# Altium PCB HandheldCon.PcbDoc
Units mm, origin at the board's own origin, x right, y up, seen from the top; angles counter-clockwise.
Board outline 100 x 100 mm, 2 copper layers (Top Layer, Bottom Layer); 39 components, 35 nets, 244 pads, 30 vias.
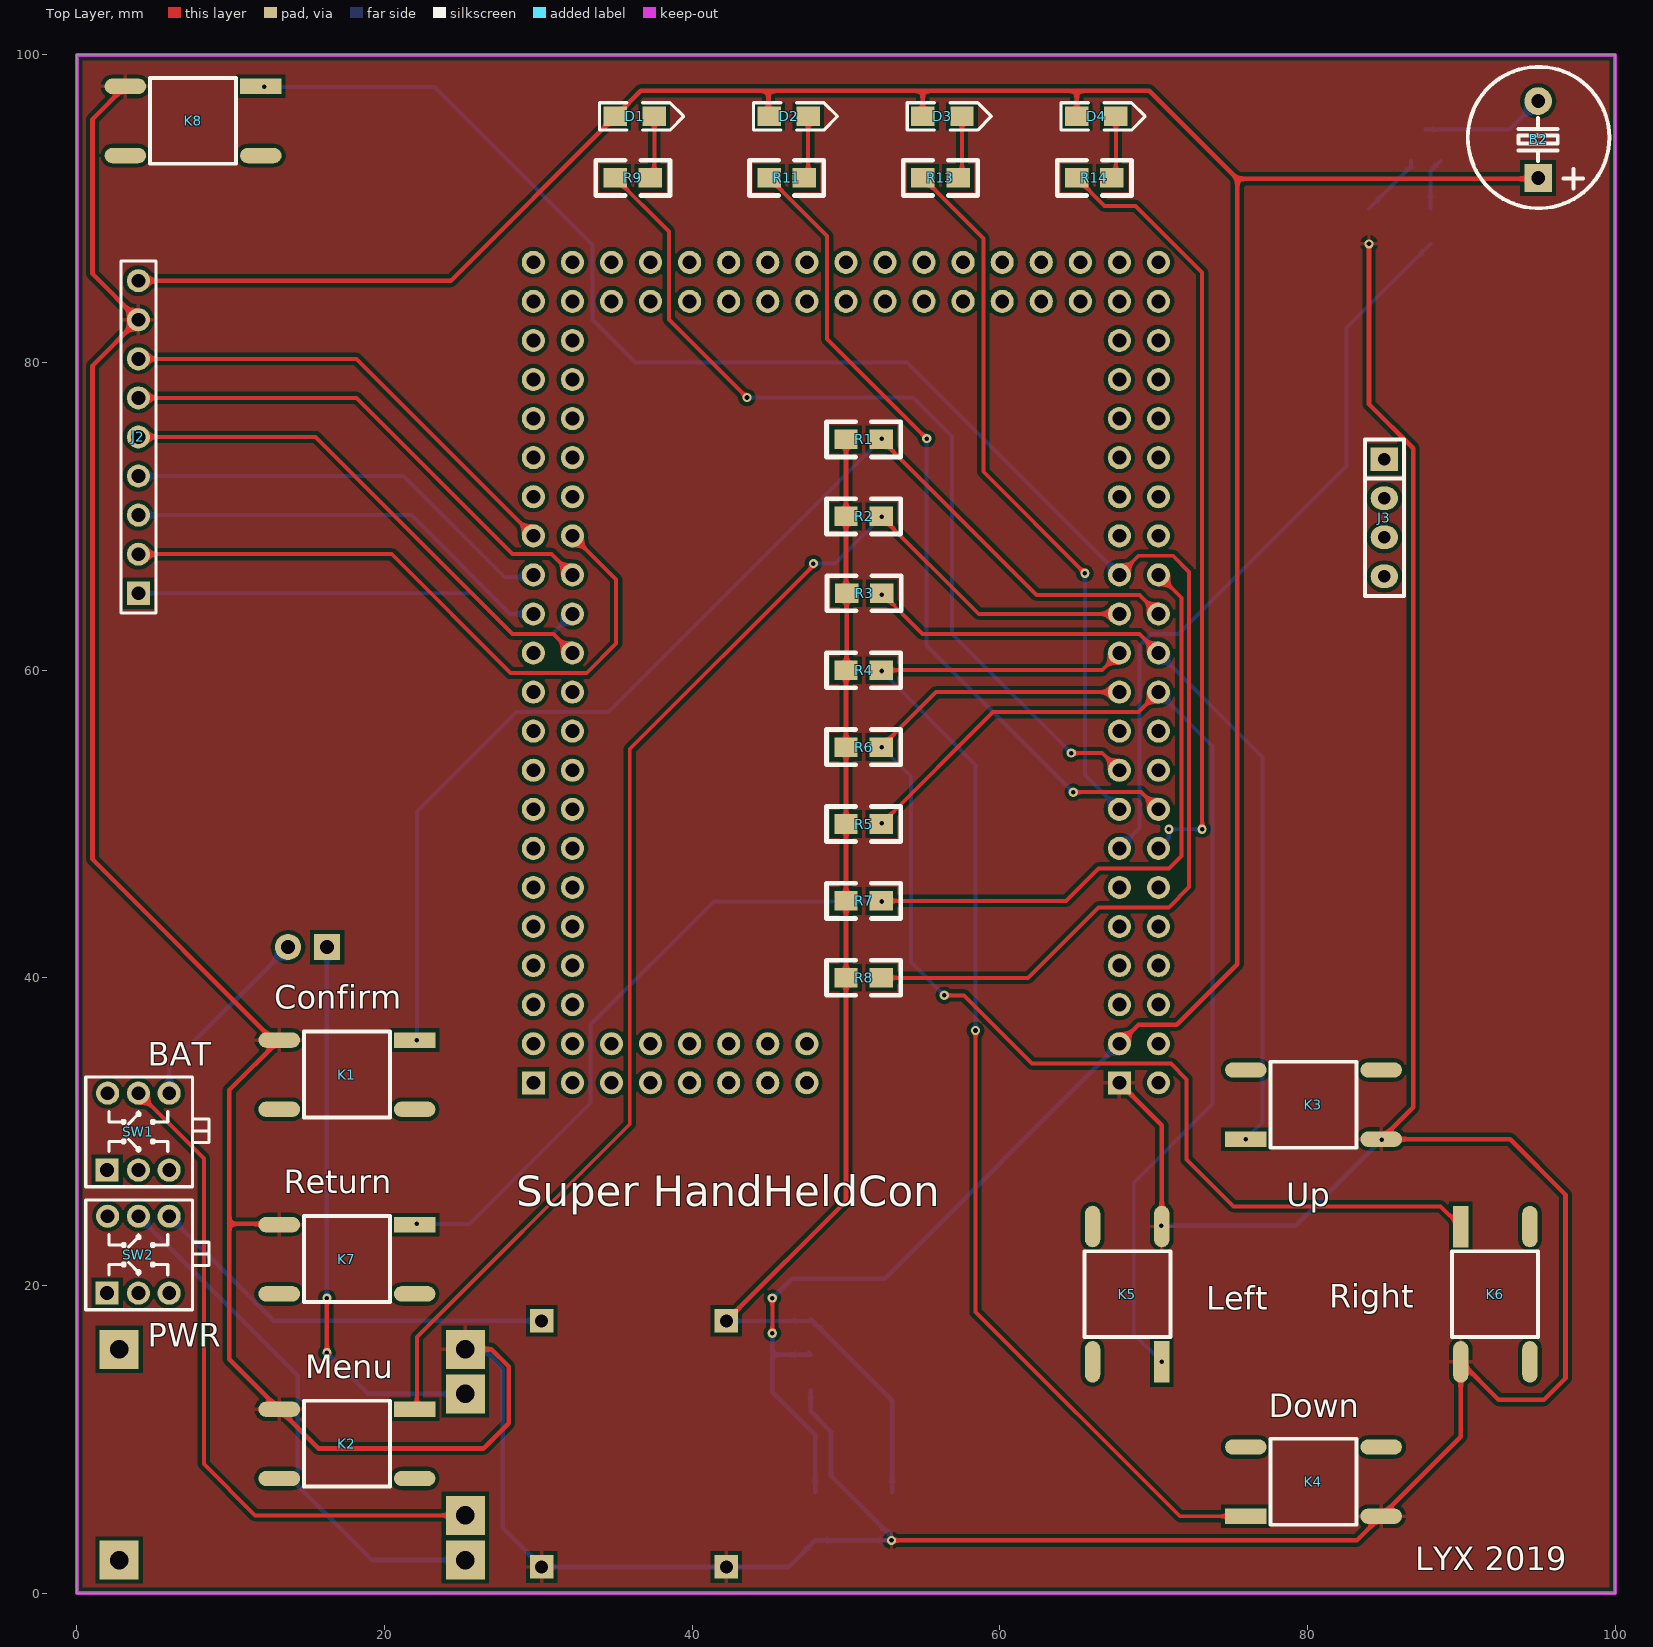
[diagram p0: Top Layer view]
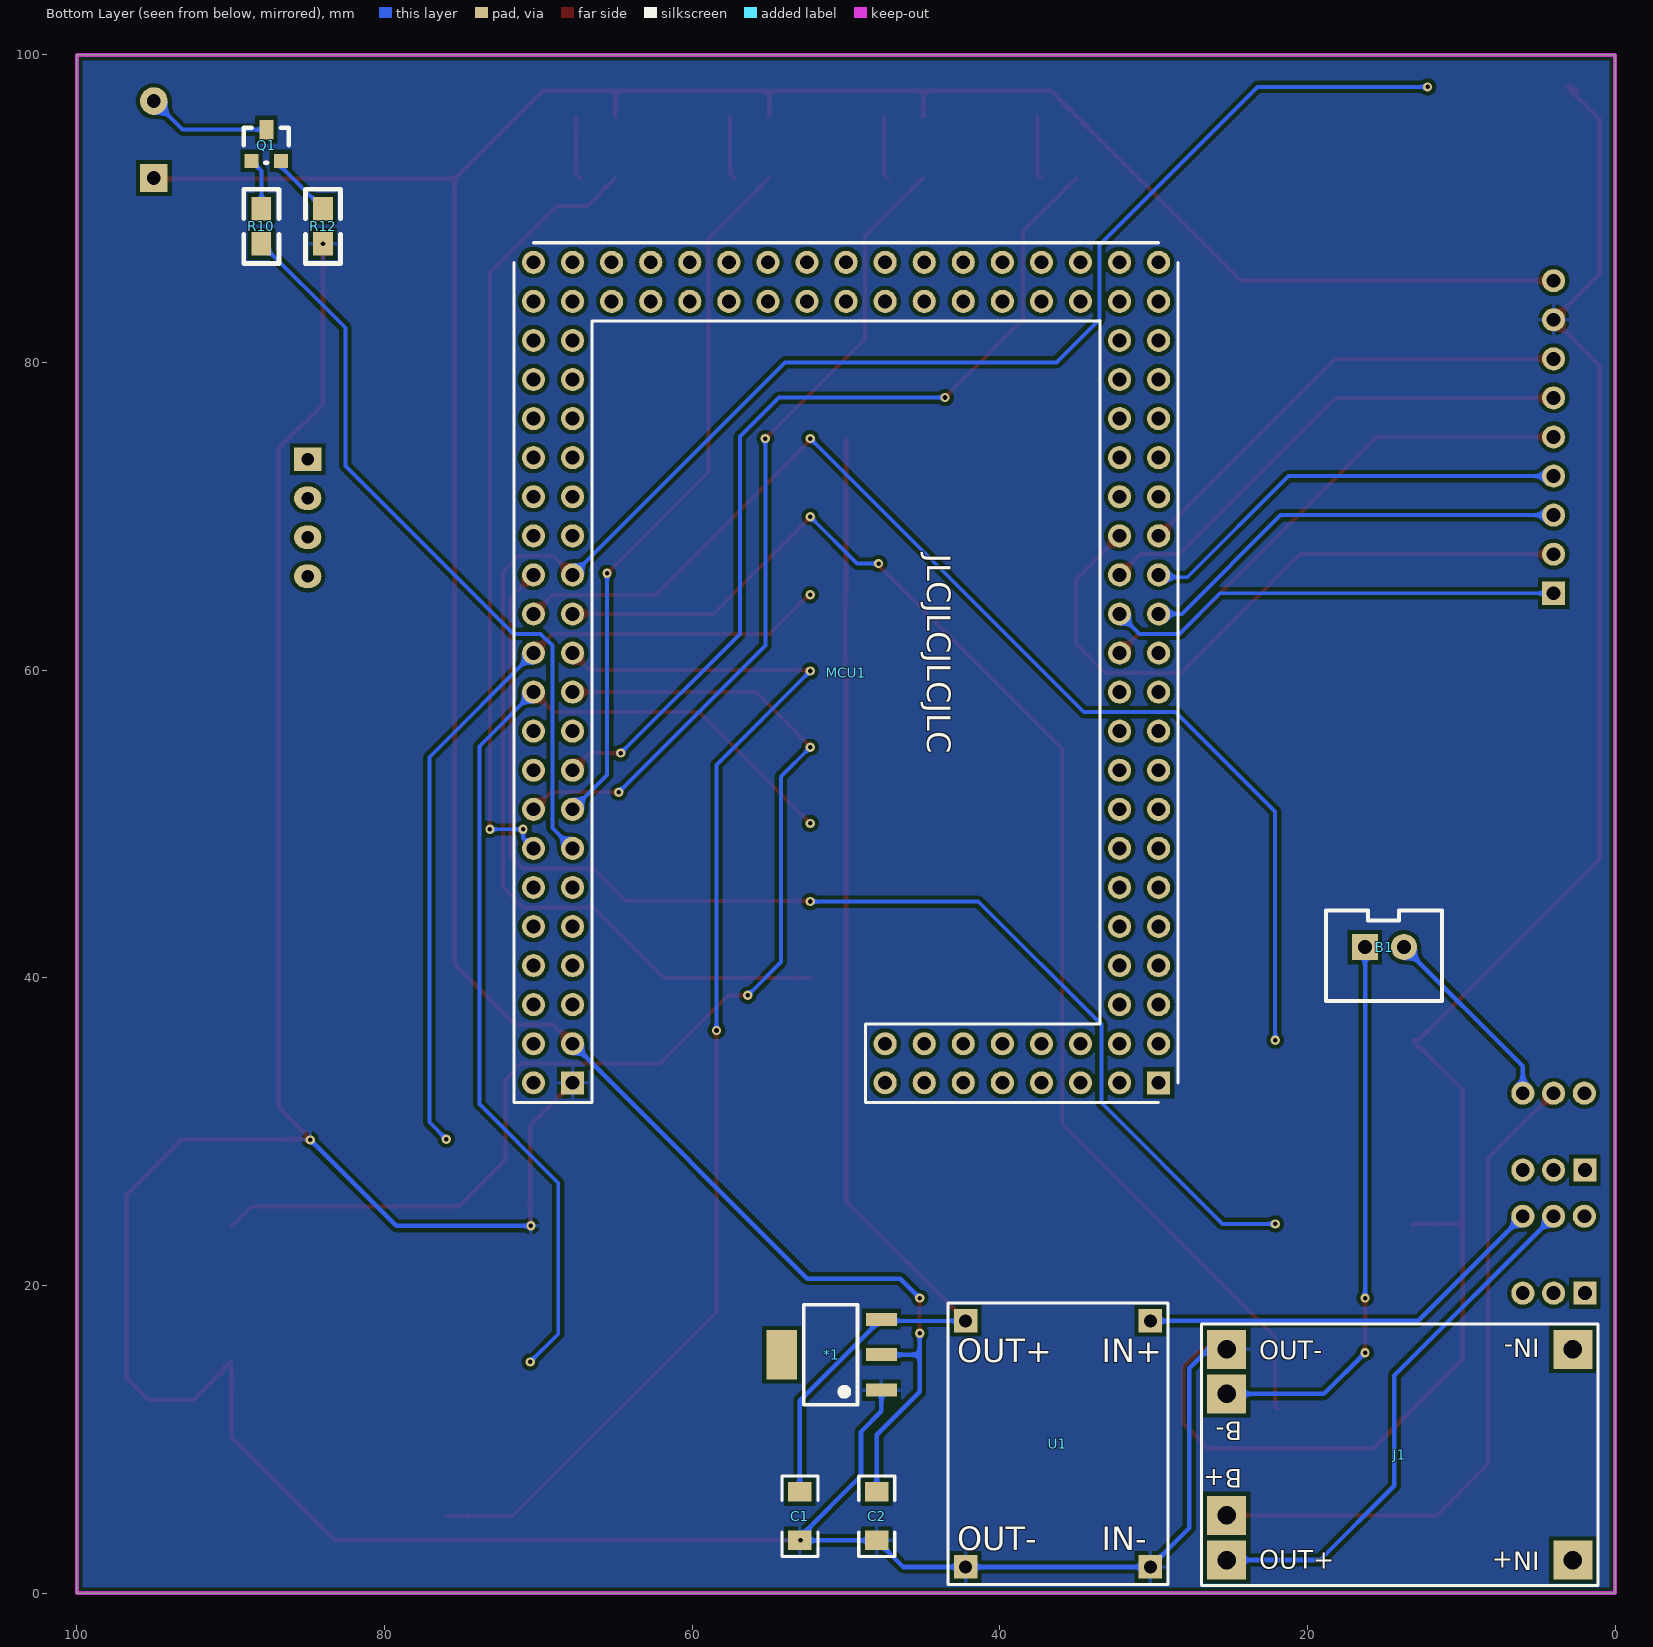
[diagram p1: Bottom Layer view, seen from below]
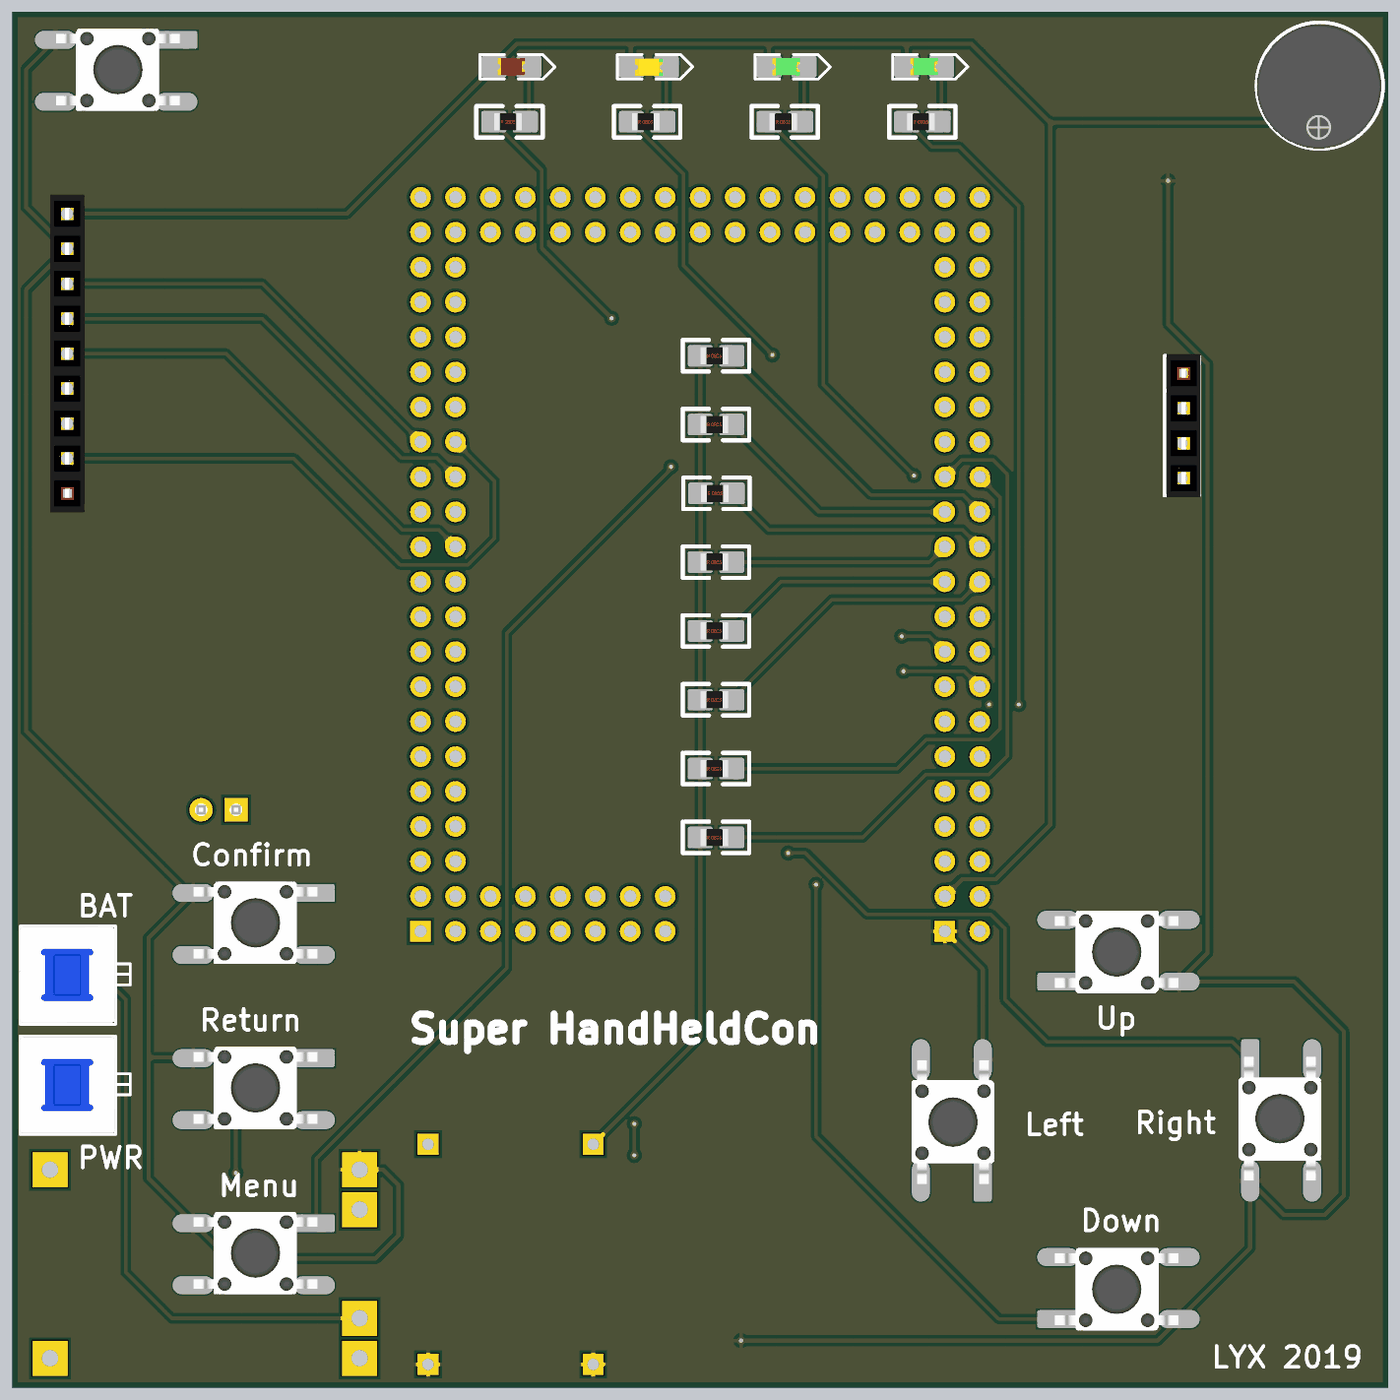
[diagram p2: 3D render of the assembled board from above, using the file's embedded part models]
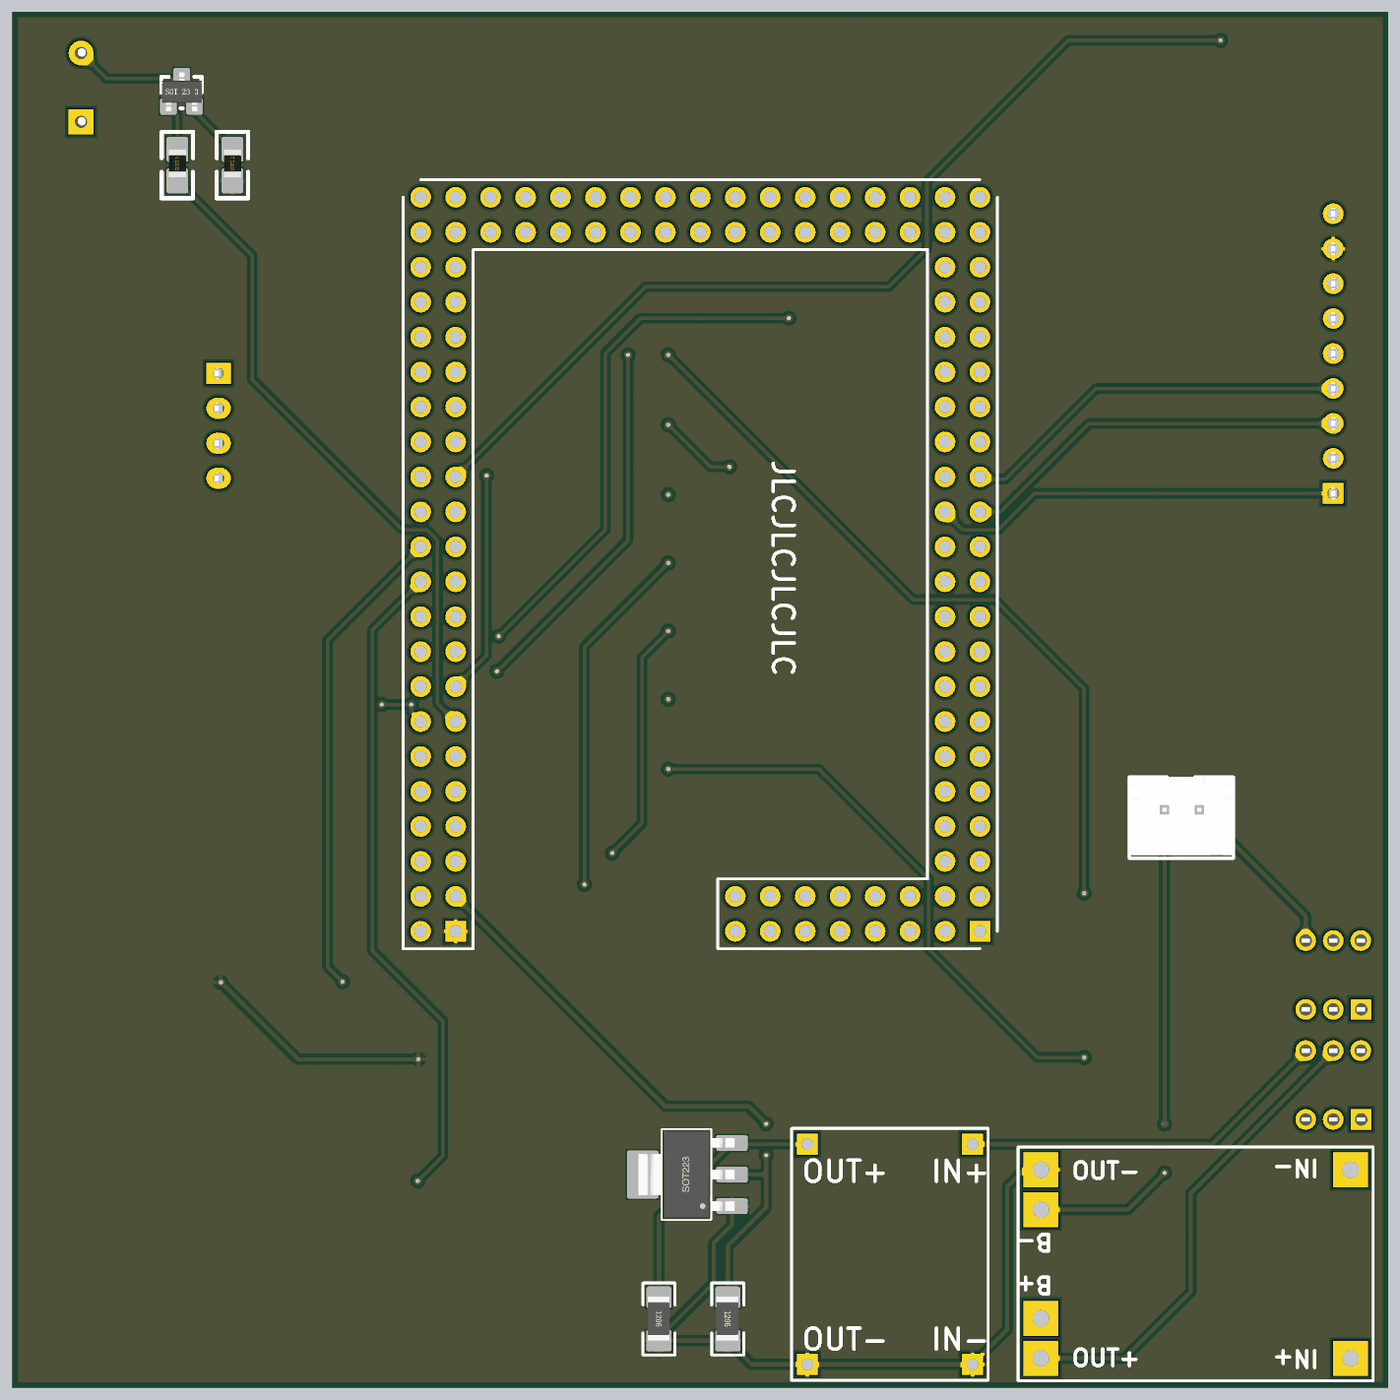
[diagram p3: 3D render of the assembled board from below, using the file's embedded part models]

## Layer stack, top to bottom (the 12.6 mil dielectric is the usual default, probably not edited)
Top Solder: solder mask 0.0102, Solder Resist, Dk 3.5
Top Layer: signal copper 0.0356
Dielectric 1: dielectric 0.32, FR-4, Dk 4.8
Bottom Layer: signal copper 0.0356
Bottom Solder: solder mask 0.0102, Solder Resist, Dk 3.5

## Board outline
0,0 0,100 100,100 100,0

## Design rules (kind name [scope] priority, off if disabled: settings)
Clearance [All] p1: gap=0.254 ignorepadtopadclearanceinfootprint=TRUE
DiffPairsRouting [All] p1: maxlimit=8 minlimit=0.254 mostfreqgap=0.254 toplayer_minwidth=0.381 toplayer_maxwidth=8 toplayer_prefwidth=0.381 bottomlayer_minwidth=0.381 bottomlayer_maxwidth=8 bottomlayer_prefwidth=0.381 maxuncoupledlength=12.7
HoleSize [All] p1: absolutevalues=TRUE maxlimit=6.35 minlimit=0.3 maxpercent=80.000 minpercent=20.000
MinimumSolderMaskSliver [All] p1: minsoldermaskwidth=0.152
PasteMaskExpansion [All] p1: expansion=0.15
PolygonConnect [All] p1: connectstyle=Relief reliefconductorwidth=0.254 reliefentries=4 polygonreliefangle="90 Angle" airgapwidth=0.254
RoutingVias [All] p1: holewidth=0.711 width=1.27 viastyle="Through Hole" minholewidth=0.3 minwidth=0.6 maxholewidth=6.35 maxwidth=7
SilkToSilkClearance [All] p1: silktosilkclearance=0
SilkToSolderMaskClearance [IsPad] p1: minsilkscreentomaskgap=0 clearancetoexposedcopper=TRUE
SolderMaskExpansion [All] p1: expansion=0.102
Width [All] p1: maxlimit=2.54 minlimit=0.254 preferedwidth=0.254
24 further rules are at their usual default settings.

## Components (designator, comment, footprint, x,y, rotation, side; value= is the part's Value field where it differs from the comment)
*1 "3Vout" ASM1117_3.3V 51,15.5 r90 bottom
B1 "Bat" XH2.54-LI-2P 15,42 r180 bottom
B2 "BEEP" "BEEP 5x9x5.5" 95,92 r90 top
C1 "C 1uF" 1206C 53,5 r270 bottom
C2 "C  1uF" 1206C 48,5 r270 bottom
D1 "LED" LED-0805R 35,96 r0 top
D2 "LED" LED-0805Y 45,96 r0 top
D3 "LED" LED-0805B 55,96 r0 top
D4 "LED" LED-0805G 65,96 r0 top
J1 "MK301" TP4056 14,9 r270 bottom
J2 "Female HDR1X9" Fe-HDR1X9/2.54-S 4,65 r180 top
J3 "Female HDR1X4" Fe-HDR1X4/2.54-S 85,73.72 r0 top
K1 "KEY" SMD-6X6X8 22,36 r270 top
K2 "KEY" SMD-6X6X8 22,12 r270 top
K3 "KEY" SMD-6X6X8 75.946,29.464 r90 top
K4 "KEY" SMD-6X6X8 75.946,4.953 r90 top
K5 "KEY" SMD-6X6X8 70.577,14.988 r180 top
K6 "KEY" SMD-6X6X8 89.916,23.876 r0 top
K7 "KEY" SMD-6X6X8 22,24 r270 top
K8 "KEY" SMD-6X6X8 12,98 r270 top
MCU1 "MCU1" 核心板底座 26.5,30 r90 bottom
Q1 "PNP 8550" SOT-23 87.757,94 r180 bottom
R1 "RES 10K" 0805R 50,75 r0 top
R2 "RES 10K" 0805R 50,70 r0 top
R3 "RES 10K" 0805R 50.038,65 r0 top
R4 "RES 10K" 0805R 50,60 r0 top
R5 "RES 10K" 0805R 50,50 r0 top
R6 "RES 10K" 0805R 50,55 r0 top
R7 "RES 10K" 0805R 50,45 r0 top
R8 "RES 10K" 0805R 50,40 r0 top
R9 "RES 470R" 0805R 35,92 r0 top
R10 "RES 470R" 0805R 88,90 r270 bottom
R11 "RES 470R" 0805R 45,92 r0 top
R12 "RES 22R" 0805R 84,90 r270 bottom
R13 "RES 470R" 0805R 55,92 r0 top
R14 "RES 470R" 0805R 65,92 r0 top
SW1 "KFT" "KFT DIP-7X7" 4,30 r0 top
SW2 "KFT" "KFT DIP-7X7" 4,22 r0 top
U1 "DCDC升压模块" DCDC升压5V 36.068,9.5 r180 bottom

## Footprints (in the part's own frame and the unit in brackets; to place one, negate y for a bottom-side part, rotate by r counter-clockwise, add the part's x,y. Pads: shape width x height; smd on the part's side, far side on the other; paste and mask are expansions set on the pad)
0805R [mil]
  rect 60x50 smd: 1(0,0) 2(90,0)
  silkscreen extent -50,-45 140,45, body extent 1,-25 80,25, height 15
1206C [mil] "3.2mmx1.6mm（蒜米工坊）"
  rect 50x60 smd: 1(-62,0) 2(62,0)
  silkscreen extent -103,-46 103,46, body extent -64,-32 62,31, height 24
ASM1117_3.3V [mm] "6.4x7x1.6mm(长宽高)"
  rect 0.85x2 smd: 1(-2.3,-3.302) 2(0,-3.302) 3(2.3,-3.302)
  rect 3.2x2 smd: 5(0,3.175)
  silkscreen extent -3.25,-1.75 3.25,1.75, body extent -3.25,-3.51 3.25,3.51, height 1.65
"BEEP 5x9x5.5" [mm]
  rect 1.8x1.8 hole 0.9: 1(0,0)
  round 1.8 hole 0.9: 2(5,0)
  silkscreen extent -1.97,-4.62 7.22,4.58, body extent -1.96,-4.44 7.04,4.55, height 5.45
DCDC升压5V [mm]
  rect 1.524x1.524 hole 0.85: 1(-6.15,8.2) 2(-6.15,-7.8) 3(5.85,-7.8) 4(5.85,8.2)
  silkscreen extent -7.3,-8.95 7,9.35
Fe-HDR1X4/2.54-S [mil]
  rect 70x60 hole 32: 1(0,0)
  oval 70x60 hole 32: 2(0,-100) 3(0,-200) 4(0,-300)
  silkscreen extent -50,-350 50,50, body extent -44,-355 54,55, height 335
Fe-HDR1X9/2.54-S [mm]
  rect 1.5x1.5 hole 0.9: 1(0,0)
  round 1.5 hole 0.9: 2(0,-2.54) 3(0,-5.08) 4(0,-7.62) 5(0,-10.16) 6(0,-12.7) 7(0,-15.24) 8(0,-17.78) 9(0,-20.32)
  silkscreen extent -1.14,-21.59 1.14,1.27, body extent -1.25,-21.72 1.25,1.4, height 3.2
"KFT DIP-7X7" [mm] "自锁开关，规格：7*7mm"
  rect 1.5x1.5 hole 0.9: 1(-2.032,-2.5)
  round 1.5 hole 0.9: 2(0,-2.5) 3(2,-2.5) 4(2,2.5) 5(0,2.5) 6(-2,2.5)
  silkscreen extent -3.42,-3.58 4.58,3.56, body extent -3.5,-3.5 3.5,3.5, height 11.2
LED-0805B [mil]
  rect 60x50 smd: A(0,0) K(100,0)
  silkscreen extent -40,-35 175,35, body extent 10,-25 89,25, height 32
LED-0805G [mil]
  rect 60x50 smd: A(0,0) K(100,0)
  silkscreen extent -40,-35 175,35, body extent 11,-24 89,25, height 32
LED-0805R [mil]
  rect 60x50 smd: A(0,0) K(100,0)
  silkscreen extent -40,-35 175,35, body extent 11,-24 89,25, height 32
LED-0805Y [mil]
  rect 60x50 smd: A(0,0) K(100,0)
  silkscreen extent -40,-35 175,35, body extent 11,-26 89,23, height 32
SMD-6X6X8 [mm]
  rect 1x2.7 smd: 1(0.047,-0.045)
  oval 1x2.7 smd: 2(4.547,-0.045) 3(0.047,-8.845) 4(4.547,-8.845)
  silkscreen extent -0.51,-7.24 5.08,-1.65, body extent -0.79,-8.82 5.21,0.18, height 7.95
SOT-23 [mil]
  rect 36x36 smd: B(-35,-35) E(40,-35)
  rect 36x50 smd: C(3,45)
  silkscreen extent -55,-40 60,50, body extent -54,-48 60,62, height 47
TP4056 [mm] "充电保护模块"
  rect 2.54x2.54 hole 1.2: 1(-6.85,11.25) 2(-6.85,-11.25) 3(-3.95,-11.25) 4(3.95,-11.25) 5(6.85,-11.25) 6(6.85,11.25)
  silkscreen extent -8.5,-12.9 8.5,12.9
XH2.54-LI-2P [mm] "接插件，2P"
  rect 1.7x1.7 hole 0.9: 1(-1.27,0)
  round 1.7 hole 0.9: 2(1.27,0)
  silkscreen extent -3.81,-3.51 3.74,2.37, body extent -3.77,-3.3 3.77,2.4, height 7.05
核心板底座 [mm]
  rect 1.5x1.5 hole 0.9: 1(3.175,41.275) 114(3.175,3.175)
  round 1.5 hole 0.9: 2(3.175,43.815) 3(5.715,41.275) 4(5.715,43.815) 5(8.255,41.275) 6(8.255,43.815) 7(10.795,41.275) 8(10.795,43.815) 9(13.335,41.275) 10(13.335,43.815) 11(15.875,41.275) 12(15.875,43.815) 13(18.415,41.275) 14(18.415,43.815) 15(20.955,41.275) 16(20.955,43.815) 17(23.495,41.275) 18(23.495,43.815) 19(26.035,41.275) 20(26.035,43.815) 21(28.575,41.275) 22(28.575,43.815) 23(31.115,41.275) 24(31.115,43.815) 25(33.655,41.275) 26(33.655,43.815) 27(36.195,41.275) 28(36.195,43.815) 29(38.735,41.275) 30(38.735,43.815) 31(41.275,41.275) 32(41.275,43.815) 33(43.815,41.275) 34(43.815,43.815) 35(46.355,41.275) 36(46.355,43.815) 37(48.895,41.275) 38(48.895,43.815) 39(51.435,41.275) 40(51.435,43.815) 41(53.975,41.275) 42(53.975,43.815) 43(56.515,41.275) 44(56.515,43.815) 45(53.975,38.735) 46(56.515,38.735) 47(53.975,36.195) 48(56.515,36.195) 49(53.975,33.655) 50(56.515,33.655) 51(53.975,31.115) 52(56.515,31.115) 53(53.975,28.575) 54(56.515,28.575) 55(53.975,26.035) 56(56.515,26.035) 57(53.975,23.495) 58(56.515,23.495) 59(53.975,20.955) 60(56.515,20.955) 61(53.975,18.415) 62(56.515,18.415) 63(53.975,15.875) 64(56.515,15.875) 65(53.975,13.335) 66(56.515,13.335) 67(53.975,10.795) 68(56.515,10.795) 69(53.975,8.255) 70(56.515,8.255) 71(56.515,5.715) 72(56.515,3.175) 73(53.975,5.715) 74(53.975,3.175) 75(51.435,5.715) 76(51.435,3.175) 77(48.895,5.715) 78(48.895,3.175) 79(46.355,5.715) 80(46.355,3.175) 81(43.815,5.715) 82(43.815,3.175) 83(41.275,5.715) 84(41.275,3.175) 85(38.735,5.715) 86(38.735,3.175) 87(36.195,5.715) 88(36.195,3.175) 89(33.655,5.715) 90(33.655,3.175) 91(31.115,5.715) 92(31.115,3.175) 93(28.575,5.715) 94(28.575,3.175) 95(26.035,5.715) 96(26.035,3.175) 97(23.495,5.715) 98(23.495,3.175) 99(20.955,5.715) 100(20.955,3.175) 101(18.415,5.715) 102(18.415,3.175) 103(15.875,5.715) 104(15.875,3.175) 105(13.335,5.715) 106(13.335,3.175) 107(10.795,5.715) 108(10.795,3.175) 109(8.255,5.715) 110(8.255,3.175) 111(5.715,5.715) 112(5.715,3.175) 113(3.175,5.715) 115(5.715,8.255) 116(3.175,8.255) 117(5.715,10.795) 118(3.175,10.795) 119(5.715,13.335) 120(3.175,13.335) 121(5.715,15.875) 122(3.175,15.875) 123(5.715,18.415) 124(3.175,18.415) 125(5.715,20.955) 126(3.175,20.955)
  silkscreen extent 1.91,1.9 57.78,45.09

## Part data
*1: library part LM1117
B1: library part Bettry
B2: "蜂鸣器"
C1 C2: library part CAP1206, "Capacitor"
MCU1: library part 核心板插座
Q1: library part PNP, "PNP三极管"
R1 R2 R3 R4 R5 R6 R7 R8 R9 R10 R11 R12 R13 R14: library part RES
SW1 SW2: library part KFT_7X7-DIP, "Self-locking Switch"

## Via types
v1: diameter 0.6, hole 0.3, Top Layer to Bottom Layer, 30 vias

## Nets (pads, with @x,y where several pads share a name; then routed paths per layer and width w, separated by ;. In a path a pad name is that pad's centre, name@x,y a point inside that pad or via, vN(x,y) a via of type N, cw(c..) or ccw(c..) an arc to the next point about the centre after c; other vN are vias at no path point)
3V3: *1.2 B2.1 C2.1 D1.A D2.A D3.A D4.A J2.9 MCU1.3 | length 210.2
  Top Layer w0.254: v1(45.212,16.891) v1(45.212,19.177)
  Top Layer w0.3: J2.9 24.32,85.32 D1.A 36.663,97.663 44.958,97.663 ; D2.A 44.958,96.042 44.958,97.663 ; D3.A 54.991,96.009 54.991,97.663 ; D4.A 65,97.663 ; MCU1.3 69.017,36.957 71.501,36.957 75.438,40.894 75.438,91.948 ; B2.1 94.948,91.948 75.438,91.948 ; 44.958,97.663 54.991,97.663 ; 54.991,97.663 65,97.663 ; 65,97.663 69.723,97.663 75.438,91.948
  Bottom Layer w0.3: v1(45.212,16.891) 45.212,15.494 ; v1(45.212,19.177) 46.482,20.447 52.507,20.447 MCU1.3 ; *1.2@47.577,15.621 *1.2 47.692,15.494 45.212,15.494 ; C2.1 48,10.293 45.212,13.081 45.212,15.494
5V: *1.3 C1.1 R1.1 R2.1 R3.1 R4.1 R5.1 R6.1 R7.1 R8.1 U1.1 | length 79.5
  Top Layer w0.3: U1.1 50,25.482 R8.1 R7.1 R5.1 R6.1 R4.1 50.038,60.038 R3.1 50,65.038 R2.1 R1.1
  Bottom Layer w0.254: U1.1 47.598,17.7 *1.3
  Bottom Layer w0.3: *1.3 53,12.498 C1.1
GND: *1.1 C1.2 C2.2 J1.2 J2.8 K1.3 K2.3 K3.3 K4.3 K5.3 K6.3 K7.3 K8.3 MCU1.1 R12.2 U1.2 U1.3 | length 343
  Top Layer w0.3: K8.3@2.432,97.609 2.777,97.953 K8.3 1.016,95.814 1.016,85.764 J2.8 1.016,79.796 1.016,47.714 12.777,35.953 K1.3 9.906,32.704 9.906,24.003 ; K7.3 13.105,24.003 9.906,24.003 ; J1.2 26.949,15.85 28.067,14.732 28.067,11.049 26.416,9.398 15.71,9.398 K2.3 9.906,15.202 9.906,24.003 ; v1(52.959,3.429) 83.22,3.429 K4.3 89.963,10.171 K6.3 92.421,12.573 95.377,12.573 96.774,13.97 96.774,25.908 93.171,29.511 89.107,29.511 K3.3 86.868,31.588 86.868,74.422 84,77.29 v1(84,87.714) ; MCU1.1 70.53,30.42 K5.3@70.53,23.876
  Bottom Layer w0.3: J1.2 26.441,15.85 27.686,14.605 27.686,4.232 U1.3 U1.2 46.275,1.7 C2.2 C1.2 ; *1.1 47.698,11.811 49.022,10.487 49.022,7.62 C1.2@53,3.642 ; v1(70.485,23.876) 79.248,23.876 v1(84.836,29.464)
NetB1_1: B1.1 J1.3 | length 36.5
  Top Layer w0.3: v1(16.256,15.621) v1(16.256,19.177)
  Bottom Layer w0.254: B1.1@16.256,41.986 B1.1
  Bottom Layer w0.3: v1(16.256,15.621) 18.927,12.95 J1.3 ; v1(16.256,19.177) B1.1@16.256,41.986
NetB1_2: B1.2 SW1.4 | length 12.7
  Bottom Layer w0.3: SW1.4 6,34.27 B1.2
NetB2_2: B2.2 Q1.C | length 8.1
  Bottom Layer w0.254: Q1.C 93.143,95.143 B2.2
NetD1_K: D1.K R9.2 | length 4.1
  Top Layer w0.254: R9.2 37.54,92.254 D1.K
NetD2_K: D2.K R11.2 | length 4.1
  Top Layer w0.254: R11.2 47.54,92.254 D2.K
NetD3_K: D3.K R13.2 | length 4.1
  Top Layer w0.254: R13.2 57.54,92.254 D3.K
NetD4_K: D4.K R14.2 | length 4.1
  Top Layer w0.254: R14.2 67.54,92.254 D4.K
NetJ1_4: J1.4 SW1.5 | length 44.3
  Top Layer w0.254: SW1.5 8.255,28.245 8.255,8.382 11.587,5.05 J1.4
NetQ1_B: Q1.B R10.1 | length 3.4
  Bottom Layer w0.254: R10.1 88,92.465 Q1.B
NetQ1_E: Q1.E R12.1 | length 4.2
  Bottom Layer w0.254: R12.1 86.741,92.741 Q1.E
NetSW2_4: SW2.4 U1.4 | length 27
  Bottom Layer w0.3: SW2.4 12.8,17.7 U1.4
PA4: J2.5 MCU1.91 | length 34
  Top Layer w0.254: J2.5 15.518,75.16 28.321,62.357 30.973,62.357 MCU1.91
PA5: J2.3 MCU1.90 | length 28.3
  Bottom Layer w0.254: J2.3 21.741,70.08 28.166,63.655 MCU1.90
PA6: J2.1 MCU1.89 | length 29.8
  Bottom Layer w0.254: J2.1 25.678,65 28.321,62.357 30.917,62.357 MCU1.89
PA7: J2.4 MCU1.88 | length 28.5
  Bottom Layer w0.254: J2.4 21.233,72.62 27.813,66.04 29.52,66.04 MCU1.88
PB0: J2.2 MCU1.85 | length 43.2
  Top Layer w0.254: J2.2 20.471,67.54 28.194,59.817 33.147,59.817 35.052,61.722 35.052,65.898 MCU1.85
PC4: J2.6 MCU1.87 | length 33
  Top Layer w0.254: J2.6 18.185,77.7 28.321,67.564 30.846,67.564 MCU1.87
PC5: J2.7 MCU1.86 | length 30.4
  Top Layer w0.254: J2.7 18.17,80.24 MCU1.86
PC11: K7.1 MCU1.28 R7.2 | length 81.5
  Top Layer w0.254: R7.2 64.304,45 66.421,47.117 70.993,47.117 71.801,47.925 71.801,64.709 MCU1.28
  Bottom Layer w0.254: v1(22.098,24.003) 25.527,24.003 33.401,31.877 33.401,36.957 41.402,44.958 v1(52.324,44.958)
PC12: K8.1 MCU1.27 R8.2 | length 120
  Top Layer w0.254: R8.2 61.844,40 66.421,44.577 70.993,44.577 72.309,45.893 72.309,66.375 71.247,67.437 69.017,67.437 MCU1.27
  Bottom Layer w0.254: v1(12.192,97.917) 23.241,97.917 33.528,87.63 33.528,82.804 36.322,80.01 53.96,80.01 MCU1.27
PD0: K1.1 MCU1.26 R1.2 | length 77.9
  Top Layer w0.254: R1.2 62.389,64.897 69.073,64.897 MCU1.26
  Bottom Layer w0.254: v1(22.098,35.941) 22.098,50.8 28.575,57.277 34.544,57.277 v1(52.324,75.057)
PD1: K2.1 MCU1.25 R2.2 | length 89.5
  Top Layer w0.254: K2.1 22.098,12.096 22.098,16.637 35.941,30.48 35.941,54.864 47.879,66.802 v1(47.879,66.929) ; R2.2 58.631,63.655 MCU1.25
  Bottom Layer w0.254: v1(47.879,66.929) 49.276,66.929 v1(52.324,69.977)
PD2: K3.1 MCU1.24 R3.2 | length 54.5
  Top Layer w0.254: R3.2 54.967,62.357 69.073,62.357 MCU1.24
  Bottom Layer w0.254: MCU1.24 77.089,54.341 77.089,30.609 v1(75.991,29.511)
  other v1: 52.324,64.897
PD3: K4.1 MCU1.23 R4.2 | length 83.2
  Top Layer w0.254: R4.2 66.66,60 MCU1.23 ; v1(58.42,36.576) 58.42,18.288 71.708,5 K4.1
  Bottom Layer w0.254: v1(52.324,59.944) 58.42,53.848 v1(58.42,36.576)
PD4: K5.1 MCU1.22 R5.2 | length 69.5
  Top Layer w0.254: R5.2 v1(52.324,50.038) 59.563,57.277 69.017,57.277 MCU1.22
  Bottom Layer w0.254: MCU1.22 73.833,55.057 73.833,31.796 68.707,26.67 68.707,16.856 v1(70.53,15.033)
PD5: K6.1 MCU1.21 R6.2 | length 77.6
  Top Layer w0.254: R6.2 55.861,58.575 MCU1.21 ; v1(56.388,38.862) 57.658,38.862 62.103,34.417 71.12,34.417 72.136,33.401 72.136,28.194 75.184,25.146 88.648,25.146 K6.1
  Bottom Layer w0.254: v1(52.324,54.991) 54.229,53.086 54.229,41.021 v1(56.388,38.862)
PG10: MCU1.17 R9.1 | length 59.6
  Top Layer w0.254: R9.1 38.481,88.519 38.481,82.804 v1(43.561,77.724) ; v1(64.643,54.61) 66.66,54.61 MCU1.17
  Bottom Layer w0.254: v1(43.561,77.724) 54.356,77.724 56.896,75.184 56.896,62.357 v1(64.643,54.61)
PG11: MCU1.16 R11.1 | length 54.1
  Top Layer w0.254: R11.1 48.768,88.232 48.768,81.534 v1(55.245,75.057) ; v1(64.77,52.07) 67.291,52.07 67.307,52.086 69.184,52.086 MCU1.16
  Bottom Layer w0.254: v1(55.245,75.057) 55.245,61.595 v1(64.77,52.07)
PG12: MCU1.15 R13.1 | length 46.3
  Top Layer w0.254: R13.1 58.928,88.072 58.928,72.898 v1(65.532,66.294)
  Bottom Layer w0.254: v1(65.532,66.294) 65.532,53.198 MCU1.15
PG13: MCU1.14 R14.1 | length 50.6
  Top Layer w0.254: R14.1 66.816,90.184 68.82,90.184 73.152,85.852 v1(73.152,49.657)
  Bottom Layer w0.254: MCU1.14 70.993,49.093 v1(70.993,49.657) v1(73.152,49.657)
PG14: MCU1.13 R10.2 | length 48.7
  Bottom Layer w0.254: MCU1.13 69.088,49.728 69.088,61.595 69.85,62.357 71.628,62.357 82.55,73.279 82.55,82.264 R10.2
VCC: J1.5 SW2.5 | length 34.7
  Bottom Layer w0.3: SW2.5 14.351,14.149 14.351,6.985 19.186,2.15 J1.5
pads on no net: *1.5 J1.1 J1.6 J3.1 J3.2 J3.3 J3.4 K1.2 K1.4 K2.2 K2.4 K3.2 K3.4 K4.2 K4.4 K5.2 K5.4 K6.2 K6.4 K7.2 K7.4 K8.2 K8.4 MCU1.2 MCU1.4 MCU1.5 MCU1.6 MCU1.7 MCU1.8 MCU1.9 MCU1.10 MCU1.11 MCU1.12 MCU1.18 MCU1.19 MCU1.20 MCU1.29 MCU1.30 MCU1.31 MCU1.32 MCU1.33 MCU1.34 MCU1.35 MCU1.36 MCU1.37 MCU1.38 MCU1.39 MCU1.40 MCU1.41 MCU1.42 MCU1.43 MCU1.44 MCU1.45 MCU1.46 MCU1.47 MCU1.48 MCU1.49 MCU1.50 MCU1.51 MCU1.52 MCU1.53 MCU1.54 MCU1.55 MCU1.56 MCU1.57 MCU1.58 MCU1.59 MCU1.60 MCU1.61 MCU1.62 MCU1.63 MCU1.64 MCU1.65 MCU1.66 MCU1.67 MCU1.68 MCU1.69 MCU1.70 MCU1.71 MCU1.72 MCU1.73 MCU1.74 MCU1.75 MCU1.76 MCU1.77 MCU1.78 MCU1.79 MCU1.80 MCU1.81 MCU1.82 MCU1.83 MCU1.84 MCU1.92 MCU1.93 MCU1.94 MCU1.95 MCU1.96 MCU1.97 MCU1.98 MCU1.99 MCU1.100 MCU1.101 MCU1.102 MCU1.103 MCU1.104 MCU1.105 MCU1.106 MCU1.107 MCU1.108 MCU1.109 MCU1.110 MCU1.111 MCU1.112 MCU1.113 MCU1.114 MCU1.115 MCU1.116 MCU1.117 MCU1.118 MCU1.119 MCU1.120 MCU1.121 MCU1.122 MCU1.123 MCU1.124 MCU1.125 MCU1.126 SW1.1 SW1.2 SW1.3 SW1.6 SW2.1 SW2.2 SW2.3 SW2.6

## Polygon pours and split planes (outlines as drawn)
GND on Bottom Layer "Top Layer-No Net" (solid, pour order 7): 0,0 0,100 100,100 100,0
GND on Top Layer "Top Layer-No Net1" (solid, pour order 8): 0,0 0,100 100,100 100,0

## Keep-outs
Keep-Out Layer:
  the board outline again, w0.254

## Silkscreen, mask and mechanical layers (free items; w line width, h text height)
Top Overlay:
  text "Confirm" at 12.827,38 h1.52
  text "BAT" at 4.6,34.29 h1.52
  text "Return" at 13.462,26 h1.52
  text "Super HandHeldCon" at 28.575,25.146 h2
  text "Up" at 78.613,25.146 h1.52
  text "Right" at 81.407,18.542 h1.52
  text "Left" at 73.406,18.415 h1.52
  text "PWR" at 4.6,16 h1.52
  text "Menu" at 14.859,13.97 h1.52
  text "Down" at 77.47,11.43 h1.52
  text "LYX 2019" at 87,1.5 h1.52
Bottom Overlay:
  text "JLCJLCJLCJLC" at 44.704,67.564 h1.52 r90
